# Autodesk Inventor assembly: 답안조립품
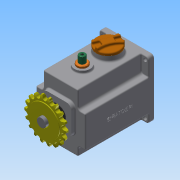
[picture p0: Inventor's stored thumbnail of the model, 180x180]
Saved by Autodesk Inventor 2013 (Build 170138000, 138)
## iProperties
Created: 2017-12
Part Number: 답안조립품
Document SubType Name: Assembly
Designer: Administrator
Mass: 2741.17 g
Surface Area: 2015.58 cm^2
Volume: 734.131 cm^3
Density: 3.7339 g/cm^3
Author: Administrator
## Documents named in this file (17)
- C:\Users\Administrator\Desktop\371208V1014\답안조립품.iam
- C:\Users\Administrator\Desktop\371208V1014\본체.ipt
- C:\Users\Administrator\Desktop\371208V1014\가변스프링.ipt
- C:\Users\Administrator\Desktop\371208V1014\멈춤나사 M3x8.ipt
- C:\Users\Administrator\Desktop\371208V1014\메인축.ipt
- C:\Users\Administrator\Desktop\371208V1014\베어링 608.ipt
- C:\Users\Administrator\Desktop\371208V1014\베어링 6003.ipt
- C:\Users\Administrator\Desktop\371208V1014\볼트 M4 x 10.ipt
- C:\Users\Administrator\Desktop\371208V1014\부시.ipt
- C:\Users\Administrator\Desktop\371208V1014\상부 캡.ipt
- C:\Users\Administrator\Desktop\371208V1014\서브축.ipt
- C:\Users\Administrator\Desktop\371208V1014\스프로킷.ipt
- C:\Users\Administrator\Desktop\371208V1014\슬라이더.ipt
- C:\Users\Administrator\Desktop\371208V1014\오일 실 8 22 7.ipt
- C:\Users\Administrator\Desktop\371208V1014\오일 실 17 32 8.ipt
- C:\Users\Administrator\Desktop\371208V1014\커버.ipt
- C:\Users\Administrator\Desktop\371208V1014\키 5 x 5 x 18.ipt
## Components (1 placed, 1 different names)
1. 가변스프링:1
